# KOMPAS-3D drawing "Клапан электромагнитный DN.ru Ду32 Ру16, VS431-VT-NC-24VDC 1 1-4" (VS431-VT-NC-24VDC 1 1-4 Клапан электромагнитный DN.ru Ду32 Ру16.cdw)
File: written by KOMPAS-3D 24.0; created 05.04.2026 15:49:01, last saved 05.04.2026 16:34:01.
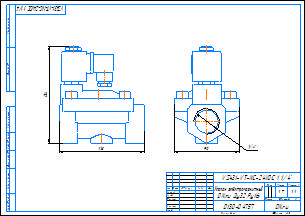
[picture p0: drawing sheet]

Document properties: c3d_UniqueCompID: ef56311e-7521-43dc-8291-0e6108b3d81d; Автор: artio; Класс точности: c; Знак неуказанной шероховатости: Шероховатость не задана; Рассекать на разрезах: Да; c3d_UniqueCompID: ef56311e-7521-43dc-8291-0e6108b3d81d; Автор: artio; Класс точности: c; Знак неуказанной шероховатости: Шероховатость не задана; Рассекать на разрезах: Да; c3d_UniqueCompID: ef56311e-7521-43dc-8291-0e6108b3d81d; Автор: artio; Класс точности: c; Знак неуказанной шероховатости: Шероховатость не задана; Рассекать на разрезах: Да; Автор: artio; Форматы листов документа: A3; Полное имя файла: VS431-VT-NC-24VDC 1 1-4 Клапан электромагнитный DN.ru Ду32 Ру16.m3d; Масса: 1.701; Наименование: Клапан электромагнитный DN.ru Ду32 Ру16; Количество листов документа: 1; Примечание: D130-04757

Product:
- Body: Тело 1  | qty 1
    Масса: 3.709873
- Part/product: Клапан электромагнитный DN.ru Ду32 Ру16  | designation VS431-VT-NC-24VDC 1 1-4
    Масса: 1.701
    Раздел спецификации: Прочие изделия
    Примечание: D130-04757
    additional columns: ef56311e-7521-43dc-8291-0e6108b3d81d; artio; c; Шероховатость не задана; Да

Views: Вид 1, Спереди
Referenced files in C:\Users\artio\OneDrive\Рабочий стол\Клапан электромагнитный DN.ru\VS431\VS431-ET-NC\: VS431-ET-NC-24VDC 3-4 Клапан электромагнитный DN.ru Ду20 Ру16.m3d, VS431-ET-NC-24VDC 3-4 Клапан электромагнитный DN.ru Ду20 Ру16.cdw
Referenced files in C:\Users\artio\OneDrive\Рабочий стол\Клапан электромагнитный DN.ru\VS431\VS431-VT-NC\: VS431-VT-NC-24VDC 1 1-4 Клапан электромагнитный DN.ru Ду32 Ру16.m3d
Referenced files in C:\Users\artio\OneDrive\Рабочий стол\Клапан электромагнитный DN.ru\VS431\VS431-VT-NC\VS431-VT-NC-24VDC\Ду32\: VS431-VT-NC-24VDC 1 1-4 Клапан электромагнитный DN.ru Ду32 Ру16.m3d
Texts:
  VS431-VT-NC-24VDC 1 1-4
  Клапан электромагнитный
  DN.ru Ду32 Ру16
  VS431-VT-NC-24VDC 1 1/4"
  VS431-VT-NC-24VDC 1 1/4"-
  Клапан электромагнитный DN.ru Ду32 Ру16
  VS431-VT-NC-24VDC 1 1-4 Клапан электромагнитный DN.ru Ду32 Ру16
Dimensions and other numbers on the sheet: 0; 3; 2; 4; 90; 1/4"; 1:1; 1; 1,7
